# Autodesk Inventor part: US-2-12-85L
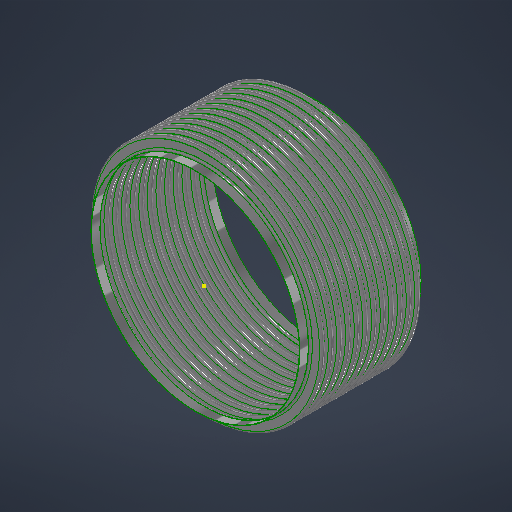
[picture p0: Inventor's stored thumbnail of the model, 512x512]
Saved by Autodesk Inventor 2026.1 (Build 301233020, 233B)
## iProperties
Category: 18 GA (0.048 THICK)
RuleStatus: InUse
Created: 2026-07
Part Number: US-2-12-85L
Project: =STOCK BELLOWS: <Stock Number><SFILL>
Material: ASTM A240-304
Description: =STOCK BELLOWS: <Stock Number>, <SID_> I.D., <SOD_> O.D., <SPLY_> PLY, <Category>, <SNET_CONS> CONS.<PITCH_><STANGENT_> TANGENT<SFILL>
Document SubType Name: Sheet Metal
Designer: LC
Stock Number: U.S-24-12-85L
Surface Area: 659.127 cm^2
Volume: 56.61 cm^3
Sheet Metal Rule: Default
Appearance: STAINLESS STEEL
NET_TUBE: 3.428
COUNTER: 1.500
PBAR: 1.214
PSET: 5.356
PLY: 2
CONS: 2
THK: 0.036
ID: 4.500
OD: 5.500
CONS_: 2
TANGENT: 0.500
PITCH: 0.375
BELLOWS_UPSET: 0.000
NET_CONS: 2
S_CONS: 0
Description_Units: 0
ID_M: 114.30 mm
OD_M: 139.70 mm
THK_M: 0.91 mm
ID_U: 4.500 in
OD_U: 5.500 in
THK_U: 0.036 in
TANGENT2: 0.500
d79: 1.000
d82: 1.000
d83: 26.000
d84: 24.000
d80: 2.571
d81: 10
SID: 2.375
SCONS_: 12
SPITCH: 0.250
SBELLOWS_UPSET: 0.000
SNET_CONS: 12
SS_CONS: 0
SCONS: 8
d174: 8
d177: 0.018
d178: 2.375
d179: 3.000
d180: 0.375
d181: 1.000
d182: 0.000
d190: 8
d191: 1
d192: 1
d193: 8
d194: 0
PART_NUMBER: U.S-24-12-85L
PRESSURE: 85
SIZE: 24.00
STANGENT_: 1.000
d214: 8
d217: 0.030
d218: 6.625
d219: 8.125
d220: 0.500
d221: 1.000
d222: 0.000
d230: 8
d231: 1
d232: 1
d233: 8
d234: 0
STANGENT: 4.000
SPLY_: 1
STHK_: 0.048
SID_: 24.000
SOD_: 26.750
SPITCH_: 1.000
STANGENT__: 1.000
SBELLOWS_UPSET_: 0.000
SDIFF_TAN: 1.000
TAN_TO_TAN: 0.750 in
d252: 2
d275: 2
d287: 0.050
d289: 0.500
d290: 0.000
d263: 2
d265: 1
d268: 2
d269: 0
d286: 2
d288: 1
d291: 2
d292: 0
SOD_NECK: 24 1/8
CFILL: .
SFILL: .
PITCH_: =, <SPITCH_> PITCH,
SREROLL: 0.750
MATTABLE: 20 GA (0.036 THICK)
MESH: ,
CSECT: 2
Author: LC
Keywords: 20 GA (0.036 THICK)
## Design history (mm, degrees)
sketch "Sketch2"
  geometry: L1 (0, -183.595)-(0, 600.956) reference; L2 (58.979, 0)-(57.15, 0); L3 (60.446, -1.467)-(66.554, -1.467); L4 (60.446, -3.296)-(66.554, -3.296); L5 (66.554, -8.058)-(60.446, -8.058); L6 (66.554, -6.229)-(60.446, -6.229); L7 (58.979, -9.525)-(57.15, -9.525); L8 (60.446, 0)-(60.446, -9.525); L9 (66.554, -4.762)-(69.85, -4.763); L10 (57.15, 0)-(57.15, -9.525); L11 (20.376, 102.841)-(20.376, 101.926); L12 (58.262, 488.877)-(58.262, 349.177); L13 (58.262, 479.352)-(58.262, 339.652); L14 (93.133, -58.817)-(93.133, -71.517); L15 (118.746, -66.401)-(118.746, -66.401); L16 (66.554, -6.229)-(66.554, -8.058); L17 (60.446, -6.229)-(60.446, -8.058); L18 (60.446, -7.144)-(66.554, -7.144); L19 (69.85, 0)-(69.85, -9.525); L20 (-66.554, -6.229)-(-66.554, -8.058); L21 (-66.554, -1.467)-(-60.446, -1.467); L22 (-66.554, -3.296)-(-60.446, -3.296); L23 (-60.446, -6.229)-(-66.554, -6.229); L24 (-66.554, -7.144)-(-60.446, -7.144); L25 (-60.446, -8.058)-(-66.554, -8.058); L26 (-60.446, -6.229)-(-60.446, -8.058); L27 (-57.15, -2.522)-(-57.15, -12.047); L28 (-60.446, -4.763)-(-57.15, -4.763); L29 (-66.554, 3.828)-(-66.554, -9.525); L30 (-68.021, 0)-(-69.85, 0); L31 (-69.85, 0)-(-69.85, -9.525); L32 (-68.021, -9.525)-(-69.85, -9.525); A1 r 1.467 centre (60.446, 0) between (58.979, 0) and (60.446, -1.467); A2 r 3.296 centre (60.446, 0) between (57.15, 0) and (60.446, -3.296); A3 r 3.296 centre (66.554, -4.762) between (66.554, -8.058) and (66.554, -1.467); A4 r 1.467 centre (66.554, -4.762) between (66.554, -6.229) and (66.554, -3.296); A5 r 1.467 centre (60.446, -9.525) between (60.446, -8.058) and (58.979, -9.525); A6 r 3.296 centre (60.446, -9.525) between (60.446, -6.229) and (57.15, -9.525); A7 r 2.381 centre (66.554, -4.762) between (66.554, -7.144) and (68.936, -4.762); A8 r 2.381 centre (60.446, -9.525) between (60.446, -7.144) and (58.064, -9.525); A9 r 1.467 centre (-66.554, -9.525) between (-66.554, -8.058) and (-68.021, -9.525); A10 r 1.467 centre (-60.446, -4.763) between (-60.446, -6.229) and (-60.446, -3.296); A11 r 2.381 centre (-60.446, -4.763) between (-60.446, -7.144) and (-58.064, -4.763); A12 r 3.296 centre (-60.446, -4.763) between (-60.446, -8.058) and (-60.446, -1.467); A13 r 2.381 centre (-66.554, -9.525) between (-66.554, -7.144) and (-68.936, -9.525); A14 r 3.296 centre (-66.554, -9.525) between (-66.554, -6.229) and (-69.85, -9.525); A15 r 1.467 centre (-66.554, 0) between (-68.021, 0) and (-66.554, -1.467); A16 r 3.296 centre (-66.554, 0) between (-69.85, 0) and (-66.554, -3.296); 10 further points
  constraints: 62 end point, 38 point on circle, 20 tangent, 16 centre point, 12 parallel, 9 midpoint, 7 vertical, 6 coincident, 6 concentric, 6 point on line, 4 equal radius, 4 perpendicular, 3 horizontal, 1 collinear, 1 horizontal alignment, 10 other
  dimensions: "THK" = 0.9144 distance of L11.start L11.end; "ID" = 114.3 distance of L11.end point (20.376, -12.374); "OD" = 139.7 distance of L12.start L12.end; "PITCH" = 9.525 distance of L12.start L13.start; "TANGENT" = 12.7 distance of L14.start L14.end; "BELLOWS_UPSET" = 0 distance of L15.start L15.end; "d43" = 114.3 diameter of L10 L1 (= ID); "d44" = 139.7 diameter of L9.end L1 (= OD); "d45" = 1.8288 distance between parallel lines of L5 L6 (computed from THK, PLY); "d46" = 3.29565 radius of A3 (computed from PITCH, THK, PLY); "UPSET_PITCH" = 9.525 distance of L2.end L7.end (derived); "SIDEWALL_ANGLE" = 0 deg angle of L3 L9 (derived); "CON_GAP" = 2.9337 distance of point (60.446, -6.229) point (60.446, -3.296) (derived); "TAN1" = 3.74046 dimension on A8 (derived); "TAN2" = 3.74046 dimension on A7 (derived); "LEG1" = 6.1087 distance of L18.start L18.end (derived); "d278" = 1.8288 distance between parallel lines of L25 L23 (derived); "d279" = 3.29565 radius of A12 (derived); "d280" = 9.525 distance of L30.end L31.end (derived); "d281" = 360 deg dimension on L21 L28 (derived); "d282" = 2.9337 distance of point (-66.554, -6.229) point (-66.554, -3.296) (derived); "d283" = 3.74046 dimension on A13 (derived); "d284" = 3.74046 dimension on A11 (derived); "d285" = 6.1087 distance of L24.start L24.end (derived); "d293" = 114.3 diameter of L27 L1 (derived); "d294" = 139.7 diameter of L31 L1 (derived)
  node "Sketch Rectangular Pattern1" dims "d31" = 25.4, "ID" = 114.3
  node "Sketch Rectangular Pattern2" dims "d39" = 25.4, "PITCH" = 9.525
revolve "CONS" stored, may be unused: angle "d48" = 90 deg
node "BELLOW MIDPLANE"
pattern_linear "Rectangular Pattern2" dims "d52" = 9.525 (= UPSET_PITCH)
sketch "Sketch5"
  geometry: C1 r 58.979 at (0, 0) reference; C2 r 57.15 at (0, 0) reference
extrude "TANGENT" new body sketch "Sketch5" distance "d53" = 12.7 (= TANGENT); taper "d54" = 0 deg
revolve "SAMETAN" stored, may be unused: angle "d65" = 90 deg
revolve "DIFFTAN" stored, may be unused: angle "d70" = 90 deg
sketch "Sketch9"
  geometry: L1 (58.391, 0)-(-58.391, 0) reference; L2 (0, -17.78)-(0, 17.78) reference; L3 (41.708, 0)-(-41.708, 0); L4 (41.708, -11.906)-(41.708, 11.906); L5 (29.008, -11.906)-(29.008, 11.906); L6 (15.418, 11.906)-(15.418, -11.906); L7 (-29.008, -11.906)-(-29.008, 11.906); L8 (-41.708, -11.906)-(-41.708, 11.906); L9 (40.914, -11.906)-(40.914, 11.906); L10 (41.708, -11.906)-(40.914, -11.906); L11 (41.708, 11.906)-(40.914, 11.906); L12 (15.815, 11.906)-(15.022, 11.906); L13 (15.022, 11.906)-(15.022, -11.906); L14 (15.022, -11.906)-(15.815, -11.906); L15 (15.815, -11.906)-(15.815, 11.906); L16 (-15.815, 11.906)-(-15.815, -11.906); L17 (-15.418, 11.906)-(-15.418, -11.906); L18 (-15.815, -11.906)-(-15.022, -11.906); L19 (-15.022, -11.906)-(-15.022, 11.906); L20 (-15.022, 11.906)-(-15.815, 11.906); L21 (-41.708, -11.906)-(-40.914, -11.906); L22 (-40.914, -11.906)-(-40.914, 11.906); L23 (-40.914, 11.906)-(-41.708, 11.906); L24 (-41.708, 11.906)-(-41.708, -11.906); L25 (41.708, -0.397)-(-41.708, -0.397); L26 (-41.708, -0.397)-(-41.708, 0.397); L27 (-41.708, 0.397)-(41.708, 0.397); L28 (41.708, 0.397)-(41.708, -0.397); L29 (-41.708, 11.906)-(41.708, 11.906); L30 (41.708, 11.906)-(41.708, 12.7); L31 (41.708, 12.7)-(-41.708, 12.7); L32 (-41.708, 12.7)-(-41.708, 11.906); L33 (41.708, -11.906)-(-41.708, -11.906); L34 (-41.708, -11.906)-(-41.708, -12.7); L35 (-41.708, -12.7)-(41.708, -12.7); L36 (41.708, -12.7)-(41.708, -11.906); 30 further points
  constraints: 68 end point, 13 midpoint, 13 parallel, 8 horizontal, 7 perpendicular, 6 equal length, 3 point on line, 2 vertical, 14 other
  dimensions: "d115" = 23.8125 distance of L4.start L4.end (derived); "d116" = 12.7 distance between parallel lines of L4 L5 (derived); "d117" = 13.58962 distance between parallel lines of L5 L6 (derived); "d125" = 44.42645 distance between parallel lines of L7 L6 (derived); "d127" = 12.7 distance between parallel lines of L8 L7 (derived); "d128" = 26.28962 distance between parallel lines of L6 L4 (derived); "d130" = 83.41607 distance between parallel lines of L8 L4 (derived); "RULER_THK" = 0.79375 distance between parallel lines of L4 L9; "d135" = 0.79375 distance of L13.end L14.end (derived); "d138" = 30.83684 distance of L13.end L16.end (derived); "d143" = 0.79375 distance of L22.end L8.end (derived); "d144" = 0.79375 distance between parallel lines of L27 L25 (derived)
extrude "RULER" join sketch "Sketch9" distance "d149" = 0.79375 (derived); taper "d150" = 0 deg
extrude "BARS" join sketch "Sketch9" distance "d151" = 0.79375 (derived); taper "d152" = 0 deg
pattern_linear "Rectangular Pattern4" dims "d155" = 30.83684 (derived)
sketch "Sketch13"
  geometry: L1 (93.149, -52.467)-(93.149, -77.867); L2 (306.019, 0)-(304.8, 0); L3 (306.019, -25.4)-(304.8, -25.4); L4 (332.765, -19.66)-(311.76, -19.66); L5 (332.765, -18.44)-(311.76, -18.44); L6 (332.765, -12.7)-(339.725, -12.7); L7 (311.76, -5.74)-(332.765, -5.74); L8 (311.76, 0)-(311.76, -25.4); L9 (304.8, 0)-(304.8, -25.4); L10 (58.254, -167.289)-(58.254, -846.739); L11 (58.254, -192.689)-(58.254, -872.139); L12 (58.254, -243.489)-(58.254, -922.939); L13 (58.254, -268.889)-(58.254, -948.339); L14 (58.254, -294.289)-(58.254, -973.739); L15 (58.254, -319.689)-(58.254, -999.139); L16 (58.254, -345.089)-(58.254, -1024.539); L17 (58.254, -218.089)-(58.254, -897.539); L18 (20.376, 103.145)-(20.376, 101.926); L19 (311.76, -6.96)-(332.765, -6.96); L20 (0, -1209.436)-(0, 321.909) reference; L21 (-62.865, 0)-(377.19, 0) reference; A1 r 5.74 centre (311.76, 0) between (306.019, 0) and (311.76, -5.74); A2 r 5.74 centre (311.76, -25.4) between (311.76, -19.66) and (306.019, -25.4); A3 r 6.96 centre (311.76, -25.4) between (311.76, -18.44) and (304.8, -25.4); A4 r 5.74 centre (332.765, -12.7) between (332.765, -18.44) and (332.765, -6.96); A5 r 6.96 centre (332.765, -12.7) between (332.765, -19.66) and (332.765, -5.74); A6 r 6.96 centre (311.76, 0) between (304.8, 0) and (311.76, -6.96); 6 further points; 1 other entity
  constraints: 38 end point, 15 point on circle, 9 tangent, 6 centre point, 6 parallel, 5 vertical alignment, 4 point on line, 4 vertical, 3 coincident, 3 concentric, 2 collinear, 2 equal radius, 1 horizontal, 1 perpendicular, 23 other
  dimensions: "SBELLOWS_UPSET_" = 0 distance of point (118.762, -66.401) point (118.762, -66.401); "STOTAL_THK_BELLOW__" = 1.2192 distance between parallel lines of L4 L5 (derived); "d224" = 6.9596 radius of A5 (derived); "d225" = 25.4 distance of L2.end L3.end (derived); "SSIDEWALL_ANGLE_" = 0 deg angle of L7 L6 (derived); "SSCON_GAP_" = 11.4808 distance of point (311.76, -18.44) point (311.76, -6.96) (derived); "d235" = 609.6 diameter of L9 L20 (derived); "d236" = 679.45 diameter of L6.end L20 (derived)
  node "Sketch Rectangular Pattern4" dims "d228" = 25.4
  node "Sketch Rectangular Pattern5" dims "d229" = 25.4
revolve "SBELLOW" stored, may be unused: angle "d197" = 90 deg
pattern_linear "Rectangular Pattern5" dims "d204" = 25.4 (derived)
revolve "STANGENT" stored, may be unused: angle "d240" = 90 deg
revolve "SSAMETAN" stored, may be unused: angle "d241" = 90 deg
revolve "SDIFFTAN" stored, may be unused: angle "d246" = 90 deg
revolve "INVCON" stored, may be unused: angle "d295" = 90 deg
pattern_linear "Rectangular Pattern6" dims "d298" = 9.525 (derived)
revolve "INVTANGENT" stored, may be unused: angle "d302" = 90 deg
revolve "INVSAMETAN" stored, may be unused: angle "d307" = 90 deg
revolve "INVDIFFTAN" stored, may be unused: angle "d312" = 90 deg
sketch "ID BELLOW MOUNT CALC"
  geometry: L1 (44.45, 0)-(38.1, 0); L2 (38.1, 0)-(38.1, 12.7); L3 (38.1, 12.7)-(44.45, 12.7); L4 (44.45, 12.7)-(44.45, 0); L5 (36.513, 12.7)-(34.684, 12.7); L6 (34.684, 12.7)-(34.684, 0); L7 (34.684, 0)-(36.513, 0); L8 (36.513, 0)-(36.513, 12.7); L9 (0, -2.54)-(0, 15.24) reference; L10 (-8.89, 0)-(53.34, 0) reference; 1 further point
  constraints: 16 end point, 5 parallel, 2 collinear, 2 horizontal, 2 perpendicular
  dimensions: "d314" = 12.7 distance of L5.end L6.end (derived); "d315" = 1.8288 distance of L5.start L5.end (derived); "IG" = 1.5875 distance between parallel lines of L2 L8; "PIPE_OD" = 88.9 diameter of L4 L9; "PIPE_WALL" = 6.35 distance of L2.end L3.end; "ID_MT_BELLOW" = 69.3674 diameter of L6 L9 (derived)
revolve "CFILL" stored, may be unused: angle "d320" = 90 deg
pattern_linear "Rectangular Pattern7" dims "d323" = 9.525 (derived)
revolve "SFILL" stored, may be unused: angle "d324" = 90 deg
pattern_linear "Rectangular Pattern8" dims "d327" = 25.4 (derived)
node "STOCK BELLOW MIDPLANE"
sketch "Sketch21"
  geometry: L1 (0, -100.013)-(0, 100.013) reference; L2 (-100.013, 0)-(100.013, 0) reference; L3 (-0.099, 71.437)-(0.099, 71.437); L4 (0.099, 71.437)-(0.099, 55.562); L5 (0.099, 55.562)-(-0.099, 55.562); L6 (-0.099, 55.562)-(-0.099, 71.437); C1 r 55.562 at (0, 0); C2 r 71.437 at (0, 0); 3 further points
  constraints: 8 end point, 2 centre point, 2 coincident, 2 parallel, 2 tangent, 1 horizontal, 1 perpendicular, 1 other
  dimensions: "d329" = 111.125 diameter of C1 (derived); "d330" = 142.875 diameter of C2 (derived); "d331" = 0.19844 distance of L3.start L3.end
extrude "CLAMSHELL" cut sketch "Sketch21" extent not by distance; stored distance "d332" = 0; taper "d333" = 0 deg
pattern_circular "Circular Pattern1" dims angle "d335" = 180 deg (derived)
node "BELLOW"
sketch "Sketch6"
  geometry: L1 (-19.05, 58.979)-(-6.35, 58.979); L2 (-6.35, 58.979)-(-6.35, 57.15); L3 (-6.35, 57.15)-(-19.05, 57.15); L4 (-19.05, 57.15)-(-19.05, 58.979); L5 (2.54, 0)-(-59.69, 0) reference; L6 (-38.1, -108.388)-(-38.1, 156.601) reference; 1 further point
  constraints: 8 end point, 2 parallel, 1 horizontal, 1 perpendicular
  dimensions: "d61" = 12.7 distance of L2.end L3.end (derived); "d62" = 1.8288 distance of L1.end L2.end (derived); "d63" = 114.3 diameter of L3 L5 (derived); "d64" = 19.05 distance between parallel lines of L4 L6 (derived)
sketch "Sketch12"
  geometry: 1 further point
sketch "Sketch14"
  geometry: L1 (-25.4, 306.019)-(0, 306.019); L2 (0, 306.019)-(0, 304.8); L3 (0, 304.8)-(-25.4, 304.8); L4 (-25.4, 304.8)-(-25.4, 306.019); L5 (5.08, 0)-(-30.48, 0) reference; L6 (0, -56.124)-(0, 336.743) reference; 1 further point
  constraints: 8 end point, 2 parallel, 1 collinear, 1 horizontal, 1 perpendicular
  dimensions: "d237" = 1.2192 distance of L3.end L1.start (derived); "d238" = 609.6 diameter of L3 L5 (derived); "d239" = 25.4 distance of L1.start L1.end (derived); "SOD_NECK" = 612.0384 diameter of L1 L5 (derived)
sketch "Sketch15"
  geometry: L1 (-56.124, 0)-(336.743, 0) reference; L2 (304.8, -304.8)-(306.019, -304.8); L3 (306.019, -304.8)-(306.019, -330.2); L4 (306.019, -330.2)-(304.8, -330.2); L5 (304.8, -330.2)-(304.8, -304.8); L6 (0, -398.78)-(0, 81.28) reference; 1 further point
  constraints: 8 end point, 2 parallel, 1 horizontal, 1 perpendicular
  dimensions: "d205" = 25.4 distance of L4.end L2.start (derived); "d206" = 1.2192 distance of L3.end L4.end (derived); "d207" = 609.6 diameter of L5 L6 (derived); "d208" = 304.8 distance between parallel lines of L1 L2 (derived)
node "TANGENT_"
node "SAME_TAN"
sketch "Sketch8"
  geometry: L1 (58.979, -19.05)-(57.15, -19.05); L2 (57.15, -19.05)-(57.15, -31.75); L3 (57.15, -31.75)-(58.979, -31.75); L4 (58.979, -31.75)-(58.979, -19.05); L5 (0, -40.64)-(0, 21.59) reference; L6 (-108.388, 0)-(156.601, 0) reference; 1 further point
  constraints: 8 end point, 2 parallel, 1 horizontal, 1 perpendicular
  dimensions: "d66" = 114.3 diameter of L2 L5 (derived); "TOTAL_THK_BELLOW" = 1.8288 distance of L2.end L3.end (derived); "d68" = 19.05 distance between parallel lines of L1 L6 (derived); "d69" = 12.7 distance of L1.end L2.end (derived)
node "DIFF_TAN"
node "Sketch Rectangular Pattern3" dims "d138" = 30.83684 (derived), "d141" = 25.4
node "SBELLOW_"
node "STANGENT_"
node "SSAME_TAN"
sketch "Sketch16"
  geometry: L1 (306.019, -304.8)-(304.8, -304.8); L2 (304.8, -304.8)-(304.8, -330.2); L3 (304.8, -330.2)-(306.019, -330.2); L4 (306.019, -330.2)-(306.019, -304.8); L5 (0, -398.78)-(0, 81.28) reference; L6 (-56.124, 0)-(336.743, 0) reference; 1 further point
  constraints: 8 end point, 2 parallel, 1 horizontal, 1 perpendicular
  dimensions: "SDIFF_TAN" = 25.4 distance of L3.end L1.start; "d243" = 1.2192 distance of L2.end L3.end (derived); "d244" = 304.8 distance between parallel lines of L1 L6 (derived); "d245" = 609.6 diameter of L2 L5 (derived)
node "SDIFF_TAN"
body "Solid15"
sketch "Sketch17"
  geometry: L1 (69.85, 12.7)-(68.021, 12.7); L2 (68.021, 12.7)-(68.021, 0); L3 (68.021, 0)-(69.85, 0); L4 (69.85, 0)-(69.85, 12.7); L5 (0, -2.54)-(0, 15.24) reference; L6 (-13.97, 0)-(83.82, 0) reference; 2 further points
  constraints: 8 end point, 2 parallel, 1 horizontal, 1 midpoint, 1 perpendicular, 1 point on line
  dimensions: "INVTANGENT" = 12.7 distance of L3.end L1.start (derived); "d300" = 1.8288 distance of L1.start L1.end (derived); "d301" = 139.7 diameter of L4 L5 (derived)
body "Solid16"
sketch "Sketch18"
  geometry: L1 (69.85, -19.05)-(68.021, -19.05); L2 (68.021, -19.05)-(68.021, -31.75); L3 (68.021, -31.75)-(69.85, -31.75); L4 (69.85, -31.75)-(69.85, -19.05); L5 (-13.97, 0)-(83.82, 0) reference; L6 (0, -40.64)-(0, 21.59) reference; 1 further point
  constraints: 8 end point, 2 parallel, 1 horizontal, 1 perpendicular
  dimensions: "d303" = 19.05 distance between parallel lines of L1 L5 (derived); "d304" = 12.7 distance of L3.end L1.start (derived); "d305" = 1.8288 distance of L2.end L3.end (derived); "d306" = 139.7 diameter of L4 L6 (derived)
body "Solid17"
sketch "Sketch19"
  geometry: L1 (69.85, -19.05)-(68.021, -19.05); L2 (68.021, -19.05)-(68.021, -31.75); L3 (68.021, -31.75)-(69.85, -31.75); L4 (69.85, -31.75)-(69.85, -19.05); L5 (0, -40.64)-(0, 21.59) reference; L6 (-13.97, 0)-(83.82, 0) reference; 1 further point
  constraints: 8 end point, 2 parallel, 1 horizontal, 1 perpendicular
  dimensions: "d308" = 12.7 distance of L1.end L2.end (derived); "d309" = 139.7 diameter of L4 L5 (derived); "d310" = 1.8288 distance of L2.end L3.end (derived); "d311" = 19.05 distance between parallel lines of L1 L6 (derived)
body "Solid18"
body "Solid19"
body "Solid20"
other parameters: "BMPL" = -152.4, "PSET" = 136.0424 (computed from OD, THK, PLY) [user parameter], "PBAR" = 30.83684 (= 0.570796 x PITCH + OD - ID) [user parameter; used in 1 equation term], "COUNTER" = 15 [user parameter], "NET_TUBE" = 87.07367 (computed from CONS_, PBAR, TANGENT) [user parameter], "S_CONS" = 0 [user parameter; used in 1 equation term], "ID_M" = 114.3 (= ID) [user parameter], "OD_M" = 139.7 (= OD) [user parameter], "THK_M" = 0.9144 (= THK) [user parameter], "ID_U" = 114.3 (= ID) [user parameter], "OD_U" = 139.7 (= OD) [user parameter], "THK_U" = 0.9144 (= THK) [user parameter], "D_UNITS" = 0 [user parameter], "TANGENT2" = 12.7 [user parameter], "TAN_TO_TAN" = 19.05 [user parameter], "OD_NECK" = 117.9576 [user parameter], "d79" = 25.4, "d80" = 65.29823 [user parameter], "d82" = 25.4, "d83" = 660.4, "d84" = 609.6, "sa_0" = 4, "FRAME_THK" = 0.79375 [user parameter], "CON_FLAT" = 13.58962 [user parameter], "SID" = 60.325 [user parameter], "SPITCH" = 6.35 [user parameter], "STANGENT_" = 25.4 [user parameter], "SBELLOWS_UPSET" = 0 [user parameter], "SS_CONS" = 0 [user parameter], "STAN_TO_TAN_" = 304.8 [user parameter], "d100" = 1.2192 [user parameter], "d191" = 25.4 [user parameter], "d194" = 0 [user parameter], "STANGENT" = 101.6 [user parameter], "d234" = 0 [user parameter], "SUPSET_PITCH_" = 25.4 [user parameter], "d269" = 0 [user parameter], "d287" = 1.27, "d289" = 12.7, "d290" = 0, "d292" = 0 [user parameter], "Thickness" = 3.048 (derived), "KFactor" = 4.4, "BendRadius" = 3.048 (derived), "BendReliefWidth" = 3.048 (derived), "BendReliefDepth" = 1.524 (derived), "CornerReliefSize" = 12.192 (derived), "SeamGap" = 0.00508, "MinimumRemnant" = 6.096 (derived), "TransitionRadius" = 3.048 (derived), "JacobiRadiusSize" = 3.048 (derived), "GapSize" = 3.048 (derived), "SREROLL" = 19.05 [user parameter], "CUR_STK_PITCH" = 25.4 [user parameter], "d328" = -152.4 (derived), "CSECTDEG" = 180 deg [user parameter]
